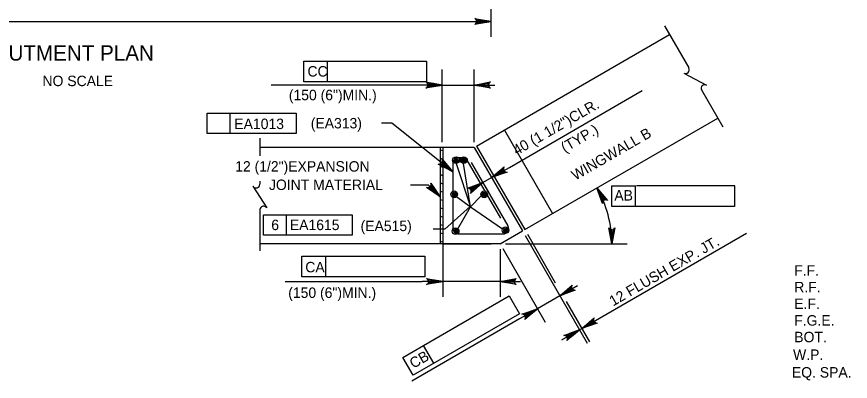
# Model space of a CAD drawing. Extents: x 634540 to 640306, y 296059 to 300275.
# Drawn here: x 638708.4 to 638948.2, y 297521.6 to 297626.3 of the extents above; entities that cross this region are included whole.
import ezdxf

# ---------------------------------------------------------------- set-up
doc = ezdxf.new("R2010")
doc.units = 0
for name, color, linetype in [('1', 7, 'Continuous'), ('10', 7, 'Continuous'), ('3', 7, 'Continuous'), ('4', 7, 'Continuous'), ('5', 7, 'Continuous')]:
    doc.layers.add(name, color=color, linetype=linetype)

# ---------------------------------------------------------------- blocks, each defined once
blk = doc.blocks.new('V')
at = {"layer": '1'}
blk.add_line((0, 0), (0, 0), dxfattribs=at)

msp = doc.modelspace()

# ---------------------------------------------------------------- linework, layer by layer
at = {"layer": '10'}
for p, q in [((638840.69, 297589.16), (638896.18, 297621.2)), ((638854.53, 297565.19), (638910.03, 297597.23)), ((638848.68, 297593.77), (638862.52, 297569.8)), ((638840.02, 297588.77), (638778.36, 297588.78)), ((638840.02, 297588.77), (638853.86, 297564.8)), ((638840.69, 297589.16), (638854.53, 297565.19)), ((638847.44, 297561.09), (638853.86, 297564.8)), ((638847.44, 297561.09), (638778.36, 297561.09)), ((638830.96, 297561.09), (638844.89, 297561.09))]:
    msp.add_line(p, q, dxfattribs=at)
at = {"layer": '3'}
for p, q in [((638844.8, 297669.3), (638844.8, 297620.56)), ((638616.53, 297624.99), (638844.8, 297624.99)), ((638791.01, 297613.58), (638797.86, 297613.58)), ((638791.01, 297607.67), (638791.01, 297613.58)), ((638797.86, 297607.67), (638797.86, 297613.58)), ((638797.86, 297613.58), (638826.31, 297613.58)), ((638826.31, 297613.58), (638826.31, 297607.67)), ((638830.79, 297590.31), (638830.79, 297611.15)), ((638840.02, 297590.31), (638840.02, 297611.15)), ((638827.84, 297606.72), (638781.61, 297606.72)), ((638826.31, 297607.67), (638791.01, 297607.67)), ((638830.79, 297606.72), (638840.02, 297606.72)), ((638842.97, 297606.72), (638845.92, 297606.72)), ((638850.13, 297583.07), (638888.35, 297605.14)), ((638763.24, 297598.67), (638788.78, 297598.67)), ((638763.24, 297592.76), (638763.24, 297598.67)), ((638769.84, 297592.76), (638769.84, 297598.67)), ((638788.78, 297598.67), (638788.78, 297592.76)), ((638816.32, 297595.81), (638813.37, 297595.81)), ((638833.84, 297581.8), (638816.32, 297595.81)), ((638788.78, 297592.76), (638763.24, 297592.76)), ((638830.19, 297588.77), (638830.19, 297561.09)), ((638830.19, 297588.15), (638830.96, 297587.95)), ((638830.96, 297588.77), (638830.96, 297559.55)), ((638830.19, 297585.76), (638830.96, 297585.56)), ((638835.38, 297585.89), (638836.58, 297585.89)), ((638837.91, 297585.12), (638847.52, 297568.47)), ((638839.16, 297584.5), (638849.67, 297566.28)), ((638830.19, 297583.38), (638830.96, 297583.17)), ((638833.84, 297584.35), (638833.84, 297565.51)), ((638834.85, 297584.16), (638838.91, 297571.72)), ((638838.91, 297571.72), (638836.9, 297584.17)), ((638842.97, 297583.67), (638847.23, 297576.28)), ((638845.02, 297580.12), (638850.13, 297583.07)), ((638830.19, 297580.99), (638830.96, 297580.78)), ((638842.52, 297578.68), (638845.02, 297580.12)), ((638826.86, 297577.99), (638821.7, 297577.99)), ((638830.19, 297574.64), (638826.85, 297577.99)), ((638830.19, 297578.6), (638830.96, 297578.39)), ((638842.13, 297579.34), (638844.11, 297575.93)), ((638879.58, 297571.87), (638879.58, 297577.77)), ((638879.58, 297577.77), (638886.4, 297577.77)), ((638886.42, 297571.87), (638886.42, 297577.77)), ((638886.63, 297577.82), (638914.93, 297577.82)), ((638914.88, 297577.77), (638914.88, 297571.87)), ((638830.19, 297576.21), (638830.96, 297576.01)), ((638838.91, 297571.72), (638841.97, 297574.93)), ((638830.19, 297573.82), (638830.96, 297573.62)), ((638834.95, 297574.69), (638838.91, 297571.72)), ((638830.19, 297571.43), (638830.96, 297571.23)), ((638838.87, 297571.85), (638831.6, 297565.33)), ((638835.31, 297565.44), (638838.91, 297571.72)), ((638838.91, 297571.72), (638848.1, 297565.4)), ((638914.88, 297571.87), (638879.58, 297571.87)), ((638779.39, 297569.47), (638804.93, 297569.47)), ((638779.39, 297563.56), (638779.39, 297569.47)), ((638785.99, 297563.56), (638785.99, 297569.47)), ((638804.93, 297569.47), (638804.93, 297563.56)), ((638830.19, 297569.05), (638830.96, 297568.84)), ((638831.6, 297565.33), (638828.19, 297565.33)), ((638830.19, 297566.66), (638830.96, 297566.45)), ((638804.93, 297563.56), (638779.39, 297563.56)), ((638830.19, 297564.27), (638830.96, 297564.06)), ((638835.38, 297563.98), (638848.34, 297563.98)), ((638854.63, 297563.47), (638872.47, 297532.57)), ((638855.3, 297563.85), (638863.33, 297549.93)), ((638876.04, 297539.74), (638918.31, 297564.15)), ((638830.19, 297561.88), (638830.96, 297561.68)), ((638848.98, 297561.09), (638884.03, 297561.09)), ((638830.96, 297559.55), (638830.96, 297545.86)), ((638847.44, 297559.55), (638847.44, 297545.86)), ((638848.21, 297559.76), (638860.39, 297538.65)), ((638790.46, 297557.53), (638797.3, 297557.53)), ((638790.46, 297551.62), (638790.46, 297557.53)), ((638797.3, 297551.62), (638797.3, 297557.53)), ((638797.3, 297557.53), (638825.76, 297557.53)), ((638825.76, 297557.53), (638825.76, 297551.62)), ((638825.76, 297551.62), (638790.46, 297551.62)), ((638785.68, 297550.29), (638825.06, 297550.29)), ((638828.01, 297550.29), (638825.06, 297550.29)), ((638847.44, 297550.29), (638830.96, 297550.29)), ((638850.39, 297550.29), (638853.34, 297550.29)), ((638864.6, 297546.2), (638869.72, 297549.15)), ((638825.41, 297531.93), (638850.06, 297546.16)), ((638850.06, 297546.16), (638853.01, 297541.04)), ((638864.6, 297546.2), (638858.18, 297542.49)), ((638866.43, 297544.57), (638873.14, 297532.96)), ((638858.18, 297542.49), (638853.07, 297539.54)), ((638853.07, 297539.54), (638822.06, 297521.63)), ((638853.01, 297541.04), (638822.44, 297523.39)), ((638870.92, 297536.79), (638876.04, 297539.74)), ((638870.26, 297536.41), (638870.92, 297536.79)), ((638870.26, 297536.41), (638865.14, 297533.46)), ((638819.48, 297528.5), (638825.41, 297531.93)), ((638828.36, 297526.82), (638825.41, 297531.93)), ((638822.44, 297523.39), (638819.48, 297528.5))]:
    msp.add_line(p, q, dxfattribs=at)
for points in [[(638844.8, 297624.99), (638840.14, 297624.12), (638840.5, 297624.37), (638840.68, 297624.68), (638840.74, 297624.99), (638840.68, 297625.31), (638840.5, 297625.62), (638840.14, 297625.87), (638844.8, 297624.99), (638840.5, 297625.62), (638840.68, 297625.31), (638844.8, 297624.99), (638840.74, 297624.99), (638840.68, 297624.68), (638844.8, 297624.99), (638840.5, 297624.37)], [(638830.79, 297606.72), (638826.13, 297605.85), (638826.49, 297606.09), (638826.68, 297606.41), (638826.73, 297606.72), (638826.68, 297607.03), (638826.49, 297607.34), (638826.13, 297607.59), (638830.79, 297606.72), (638826.49, 297607.34), (638826.68, 297607.03), (638830.79, 297606.72), (638826.73, 297606.72), (638826.68, 297606.41), (638830.79, 297606.72), (638826.49, 297606.09)], [(638840.02, 297606.72), (638844.68, 297607.59), (638844.32, 297607.34), (638844.14, 297607.03), (638844.08, 297606.72), (638844.14, 297606.41), (638844.32, 297606.09), (638844.68, 297605.85), (638840.02, 297606.72), (638844.32, 297606.09), (638844.14, 297606.41), (638840.02, 297606.72), (638844.08, 297606.72), (638844.14, 297607.03), (638840.02, 297606.72), (638844.32, 297607.34)], [(638833.84, 297581.8), (638829.66, 297584.03), (638830.09, 297584), (638830.43, 297584.13), (638830.67, 297584.34), (638830.83, 297584.61), (638830.88, 297584.97), (638830.75, 297585.39), (638833.84, 297581.8), (638830.88, 297584.97), (638830.83, 297584.61), (638833.84, 297581.8), (638830.67, 297584.34), (638830.43, 297584.13), (638833.84, 297581.8), (638830.09, 297584)], [(638845.02, 297580.12), (638848.62, 297583.21), (638848.43, 297582.81), (638848.43, 297582.45), (638848.53, 297582.15), (638848.74, 297581.91), (638849.05, 297581.73), (638849.49, 297581.69), (638845.02, 297580.12), (638849.05, 297581.73), (638848.74, 297581.91), (638845.02, 297580.12), (638848.53, 297582.15), (638848.43, 297582.45), (638845.02, 297580.12), (638848.43, 297582.81)], [(638830.19, 297574.64), (638826.28, 297577.33), (638826.71, 297577.25), (638827.07, 297577.34), (638827.33, 297577.52), (638827.51, 297577.78), (638827.6, 297578.13), (638827.52, 297578.56), (638830.19, 297574.64), (638827.6, 297578.13), (638827.51, 297577.78), (638830.19, 297574.64), (638827.33, 297577.52), (638827.07, 297577.34), (638830.19, 297574.64), (638826.71, 297577.25)], [(638842.52, 297578.68), (638838.92, 297575.59), (638839.11, 297575.98), (638839.11, 297576.35), (638839, 297576.64), (638838.8, 297576.89), (638838.48, 297577.07), (638838.04, 297577.1), (638842.52, 297578.68), (638838.48, 297577.07), (638838.8, 297576.89), (638842.52, 297578.68), (638839, 297576.64), (638839.11, 297576.35), (638842.52, 297578.68), (638839.11, 297575.98)], [(638875.29, 297577.17), (638878.38, 297573.57), (638877.98, 297573.76), (638877.62, 297573.77), (638877.32, 297573.65), (638877.08, 297573.45), (638876.9, 297573.14), (638876.87, 297572.7), (638875.29, 297577.17), (638876.9, 297573.14), (638877.08, 297573.45), (638875.29, 297577.17), (638877.32, 297573.65), (638877.62, 297573.77), (638875.29, 297577.17), (638877.98, 297573.76)], [(638879.6, 297561.09), (638878.73, 297565.75), (638878.98, 297565.39), (638879.29, 297565.21), (638879.6, 297565.15), (638879.92, 297565.21), (638880.23, 297565.39), (638880.48, 297565.75), (638879.6, 297561.09), (638880.23, 297565.39), (638879.92, 297565.21), (638879.6, 297561.09), (638879.6, 297565.15), (638879.29, 297565.21), (638879.6, 297561.09), (638878.98, 297565.39)], [(638830.96, 297550.29), (638826.3, 297549.41), (638826.66, 297549.66), (638826.84, 297549.97), (638826.9, 297550.29), (638826.84, 297550.6), (638826.66, 297550.91), (638826.3, 297551.16), (638830.96, 297550.29), (638826.66, 297550.91), (638826.84, 297550.6), (638830.96, 297550.29), (638826.9, 297550.29), (638826.84, 297549.97), (638830.96, 297550.29), (638826.66, 297549.66)], [(638847.44, 297550.29), (638852.1, 297551.16), (638851.74, 297550.91), (638851.56, 297550.6), (638851.5, 297550.29), (638851.56, 297549.97), (638851.74, 297549.66), (638852.1, 297549.41), (638847.44, 297550.29), (638851.74, 297549.66), (638851.56, 297549.97), (638847.44, 297550.29), (638851.5, 297550.29), (638851.56, 297550.6), (638847.44, 297550.29), (638851.74, 297550.91)], [(638864.6, 297546.2), (638868.2, 297549.28), (638868.02, 297548.89), (638868.01, 297548.52), (638868.12, 297548.23), (638868.33, 297547.99), (638868.64, 297547.81), (638869.08, 297547.77), (638864.6, 297546.2), (638868.64, 297547.81), (638868.33, 297547.99), (638864.6, 297546.2), (638868.12, 297548.23), (638868.01, 297548.52), (638864.6, 297546.2), (638868.02, 297548.89)], [(638858.18, 297542.49), (638854.58, 297539.4), (638854.77, 297539.8), (638854.77, 297540.16), (638854.66, 297540.46), (638854.46, 297540.7), (638854.14, 297540.88), (638853.71, 297540.92), (638858.18, 297542.49), (638854.14, 297540.88), (638854.46, 297540.7), (638858.18, 297542.49), (638854.66, 297540.46), (638854.77, 297540.16), (638858.18, 297542.49), (638854.77, 297539.8)], [(638870.92, 297536.79), (638874.52, 297539.88), (638874.34, 297539.48), (638874.33, 297539.12), (638874.44, 297538.82), (638874.64, 297538.58), (638874.96, 297538.4), (638875.39, 297538.36), (638870.92, 297536.79), (638874.96, 297538.4), (638874.64, 297538.58), (638870.92, 297536.79), (638874.44, 297538.82), (638874.33, 297539.12), (638870.92, 297536.79), (638874.34, 297539.48)], [(638870.26, 297536.41), (638866.66, 297533.32), (638866.84, 297533.72), (638866.85, 297534.08), (638866.74, 297534.38), (638866.54, 297534.62), (638866.22, 297534.8), (638865.78, 297534.83), (638870.26, 297536.41), (638866.22, 297534.8), (638866.54, 297534.62), (638870.26, 297536.41), (638866.74, 297534.38), (638866.85, 297534.08), (638870.26, 297536.41), (638866.84, 297533.72)]]:
    msp.add_lwpolyline(points, dxfattribs=at)
for points in [[(638841.85, 297625.48), (638841.85, 297624.5), (638844.8, 297624.99)], [(638827.84, 297607.21), (638827.84, 297606.23), (638830.79, 297606.72)], [(638842.97, 297607.21), (638842.97, 297606.23), (638840.02, 297606.72)], [(638847.33, 297582.02), (638847.82, 297581.17), (638845.02, 297580.12)], [(638828.01, 297550.78), (638828.01, 297549.8), (638830.96, 297550.29)], [(638850.39, 297550.78), (638850.39, 297549.8), (638847.44, 297550.29)], [(638866.91, 297548.1), (638867.41, 297547.25), (638864.6, 297546.2)], [(638855.38, 297541.44), (638855.87, 297540.59), (638858.18, 297542.49)], [(638873.23, 297538.69), (638873.73, 297537.84), (638870.92, 297536.79)], [(638867.45, 297535.36), (638867.95, 297534.51), (638870.26, 297536.41)]]:
    msp.add_lwpolyline(points, close=True, dxfattribs=at)
for centre in [(638834.77, 297585.12), (638837.05, 297585.12), (638834.23, 297575.33), (638842.85, 297575.33), (638834.65, 297564.74), (638848.99, 297565.03)]:
    msp.add_circle(centre, 0.962, dxfattribs=at)
for centre, radius, start, end in [((638835.38, 297584.35), 1.54, 90, 180), ((638836.58, 297584.35), 1.54, 30, 90), ((638847.44, 297561.09), 32.16, 359.9996, 30.0002), ((638835.38, 297565.51), 1.54, 180, 270), ((638848.34, 297565.51), 1.54, 270, 30)]:
    msp.add_arc(centre, radius, start, end, dxfattribs=at)
at = {"layer": '4'}
for p, q in [((638894.76, 297623.67), (638901.72, 297611.62)), ((638900.26, 297610.16), (638906.83, 297606.7)), ((638905.36, 297605.31), (638911.49, 297594.7)), ((638778.36, 297591.45), (638778.36, 297586.36)), ((638776.37, 297577.7), (638780.32, 297571.41)), ((638778.36, 297579.14), (638778.36, 297578.23)), ((638778.36, 297570.95), (638778.36, 297559.07))]:
    msp.add_line(p, q, dxfattribs=at)
for centre, start, end in [((638900.79, 297611.08), 240, 30), ((638906.33, 297605.75), 62.1328, 204.6714), ((638777.29, 297578.23), 210, 0), ((638779.42, 297570.85), 32.1328, 174.6714)]:
    msp.add_arc(centre, 1.07, start, end, dxfattribs=at)
at = {"layer": '5'}
for centre, radius in [((638834.78, 297585.01), 0.625), ((638834.78, 297585.01), 0.469), ((638834.78, 297585.01), 0.313), ((638834.78, 297585.01), 0.156), ((638837.03, 297585.13), 0.625), ((638837.03, 297585.13), 0.469), ((638837.03, 297585.13), 0.313), ((638837.03, 297585.13), 0.156), ((638834.38, 297575.31), 0.625), ((638834.38, 297575.31), 0.469), ((638834.38, 297575.31), 0.313), ((638834.38, 297575.31), 0.156), ((638842.75, 297575.25), 0.625), ((638842.75, 297575.25), 0.469), ((638842.75, 297575.25), 0.313), ((638842.75, 297575.25), 0.156), ((638834.84, 297564.8), 0.625), ((638849.1, 297564.97), 0.625), ((638849.1, 297564.97), 0.469), ((638834.84, 297564.8), 0.469), ((638834.84, 297564.8), 0.313), ((638834.84, 297564.8), 0.156), ((638849.1, 297564.97), 0.313), ((638849.1, 297564.97), 0.156)]:
    msp.add_circle(centre, radius, dxfattribs=at)

# ---------------------------------------------------------------- block references
at = {"layer": '3', "xscale": 0.78743606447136, "yscale": 0.78743606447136}
msp.add_blockref('V', (638899.64, 297577.82), dxfattribs=at)

# ---------------------------------------------------------------- texts
at = {"layer": '3'}
for s, height, p in [('ABUTMENT PLAN', 4.4294, (638698.18, 297613.73)), ('CC', 3, (638792.06, 297609.15)), ('NO SCALE', 3, (638715.85, 297606.4)), ('(150 (6")MIN.)', 3.0001, (638786.69, 297602.35)), ('EA1013', 3, (638771.02, 297594.07)), ('(EA313)', 3, (638793, 297594.26)), ('12 (1/2")EXPANSION', 3.0001, (638771.27, 297581.85)), ('JOINT MATERIAL', 3.0001, (638780.98, 297576.57)), ('AB', 3, (638880.3, 297573.53)), ('6', 3, (638781.65, 297565.05)), ('EA1615', 3, (638786.99, 297565.05)), ('(EA515)', 3, (638807.33, 297564.76)), ('CA', 3, (638791.43, 297552.92)), ('F.F.', 3, (638932.04, 297551.97)), ('(150 (6")MIN.)', 3.0001, (638786.52, 297545.58)), ('R.F.', 3, (638932.04, 297547.19)), ('E.F.', 3, (638932.04, 297542.41)), ('F.G.E.', 3, (638932.04, 297537.63)), ('BOT.', 3, (638932.04, 297532.85)), ('W.P.', 3, (638931.7, 297527.78)), ('EQ. SPA.', 3, (638931.36, 297522.71))]:
    msp.add_text(s, height=height, dxfattribs=at).set_placement(p)
for s, height, rotation, p in [(' 40 (1 1/2")CLR.', 3.0001, 30.0018, (638851.28, 297585.89)), ('(TYP.)', 3, 30.0018, (638866.04, 297587.21)), ('WINGWALL B', 3, 30, (638869.06, 297579.21)), ('12 FLUSH EXP. JT.', 3.0001, 30, (638879.93, 297543.1)), ('CB', 3, 30, (638822.51, 297525.2))]:
    msp.add_text(s, height=height, rotation=rotation, dxfattribs=at).set_placement(p)

doc.saveas('drawing.dxf')
